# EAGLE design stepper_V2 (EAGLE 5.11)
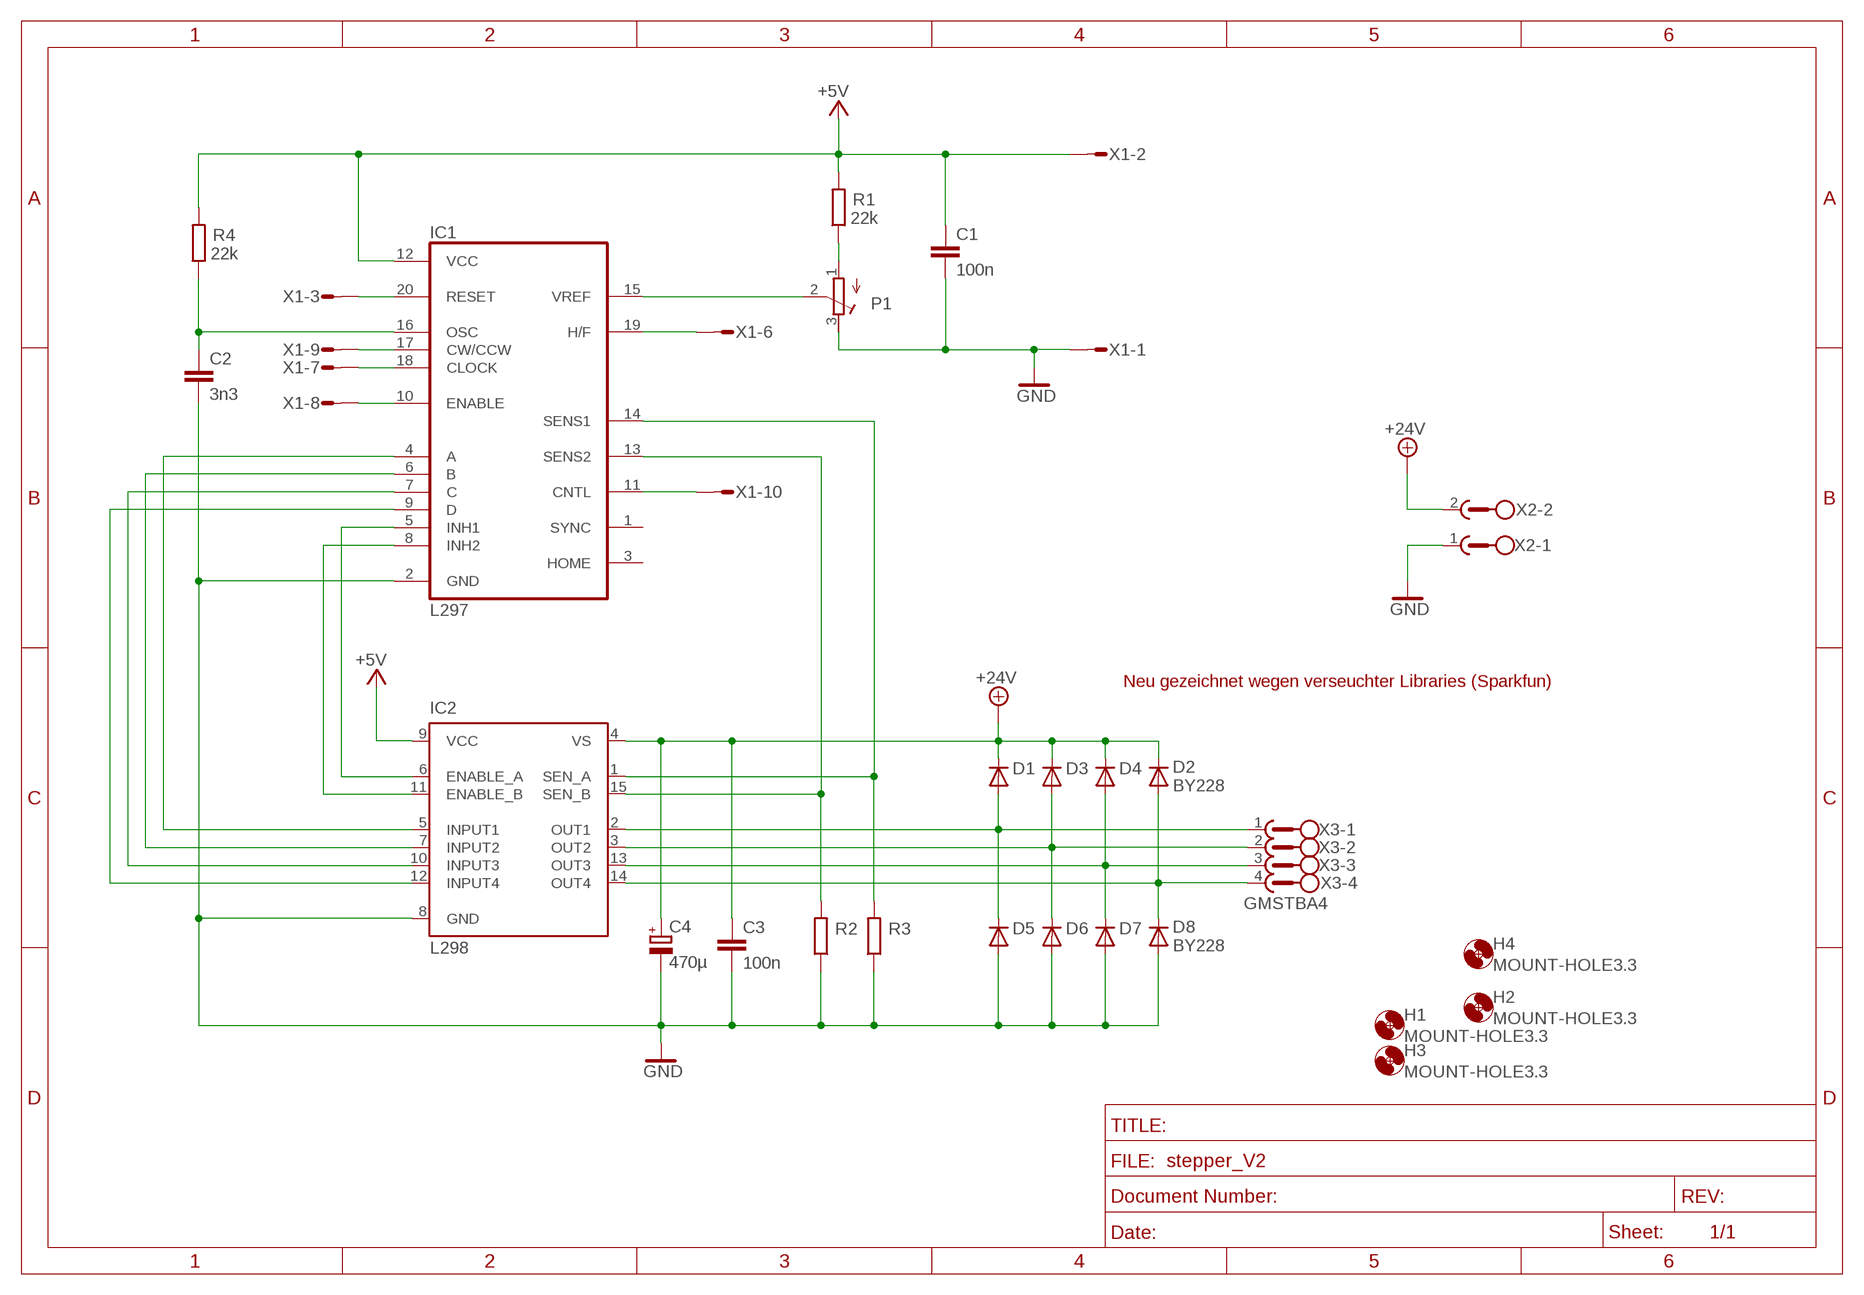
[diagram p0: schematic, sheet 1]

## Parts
C1  100n  C-EU050-024X044  [C050-024X044]
C2  3n3  C-EU050-024X044  [C050-024X044]
C3  100n  C-EU050-024X044  [C050-024X044]
C4  470µ  CPOL-EUE5-10.5  [E5-10,5]
D1  BY228  [SOD64-10]
D2  BY228  [SOD64-10]
D3  BY228  [SOD64-10]
D4  BY228  [SOD64-10]
D5  BY228  [SOD64-10]
D6  BY228  [SOD64-10]
D7  BY228  [SOD64-10]
D8  BY228  [SOD64-10]
H1  MOUNT-HOLE3.3  [3,3]
H2  MOUNT-HOLE3.3  [3,3]
H3  MOUNT-HOLE3.3  [3,3]
H4  MOUNT-HOLE3.3  [3,3]
IC1  L297  [DIL20]
IC2  L298  [MULTIWATT-15]
P1  R-TRIMM64Y  [RTRIM64Y]
R1  22k  R-EU_0207/10  [0207/10]
R2  R-EU_0411/15  [0411/15]
R3  R-EU_0411/15  [0411/15]
R4  22k  R-EU_0207/10  [0207/10]
X1  MICROMATCH-10  [MICROMATCH-10]
X2  GMSTBA2  [GMSTBA2]
X3  GMSTBA4  [GMSTBA4]

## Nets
+5V: C1.1 IC1.12(VCC) IC2.9(VCC) R1.2 R4.2 X1.2
+24V: C3.1 C4.+ D1.C D2.C D3.C D4.C IC2.4(VS) X2.2
GND: C1.2 C2.2 C3.2 C4.- D5.A D6.A D7.A D8.A IC1.2(GND) IC2.8(GND) P1.3(A) R2.1 R3.1 X1.1 X2.1
N$1: IC1.14(SENS1) IC2.1(SEN_A) R3.2
N$2: IC1.13(SENS2) IC2.15(SEN_B) R2.2
N$3: C2.1 IC1.16(OSC) R4.1
N$4: IC1.4(A) IC2.5(INPUT1)
N$5: IC1.6(B) IC2.7(INPUT2)
N$6: IC1.7(C) IC2.10(INPUT3)
N$7: IC1.9(D) IC2.12(INPUT4)
N$8: IC1.5(INH1) IC2.6(ENABLE_A)
N$9: IC1.8(INH2) IC2.11(ENABLE_B)
N$10: IC1.20(RESET) X1.3
N$11: IC1.15(VREF) P1.2(S)
N$12: P1.1(E) R1.1
N$13: IC1.18(CLOCK) X1.7
N$14: D1.A D5.C IC2.2(OUT1) X3.1
N$15: D3.A D6.C IC2.3(OUT2) X3.2
N$16: D4.A D7.C IC2.13(OUT3) X3.3
N$17: D2.A D8.C IC2.14(OUT4) X3.4
N$18: IC1.10(ENABLE) X1.8
N$19: IC1.17(CW/CCW) X1.9
N$20: IC1.11(CNTL) X1.10
N$21: IC1.19(H/F) X1.6
Unconnected: IC1.1(SYNC) IC1.3(HOME) X1.4 X1.5

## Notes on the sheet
- Neu gezeichnet wegen verseuchter Libraries (Sparkfun)

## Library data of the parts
C1-C3 = rcl-JP:C-EU: CAPACITOR, European symbol
C4 = rcl-JP:CPOL-EU: POLARIZED CAPACITOR, European symbol
D1-D8 = diode:BY228: DIODE
H1-H4 = holes:MOUNT-HOLE: MOUNTING HOLE with drill center marker
IC1 = st-microelectronics:L297: STEPPER MOTOR CONTROLLER; MPN: L297/1; OC_FARNELL: 1094209; OC_NEWARK: 56P8258
IC2 = st-microelectronics:L298: DUAL FULL-BRIDGE DRIVER; MPN: L298N; OC_FARNELL: 1589425; OC_NEWARK: 32M1527
P1 = rcl-JP:R-TRIMM: Trimm resistor
R1-R4 = rcl-JP:R-EU_: RESISTOR, European symbol
X1 = con-amp-micromatch:MICROMATCH-10: MicroMaTch 10 8-215464-0 / 1-215464-0 Drawing Number C-215464 DDEController.pdf; MF: FARNELL; MPN: 8-215464-0; OC_FARNELL: 3784654; OC_NEWARK: 19J6430
X2 = con-phoenix-762:GMSTBA2: PHOENIX; MF: FARNELL; MPN: 1757242; OC_FARNELL: 3705171; OC_NEWARK: 71C4161
X3 = con-phoenix-762:GMSTBA4: PHOENIX; MF: FARNELL; MPN: 1757268; OC_FARNELL: 3705195; OC_NEWARK: 71C4163

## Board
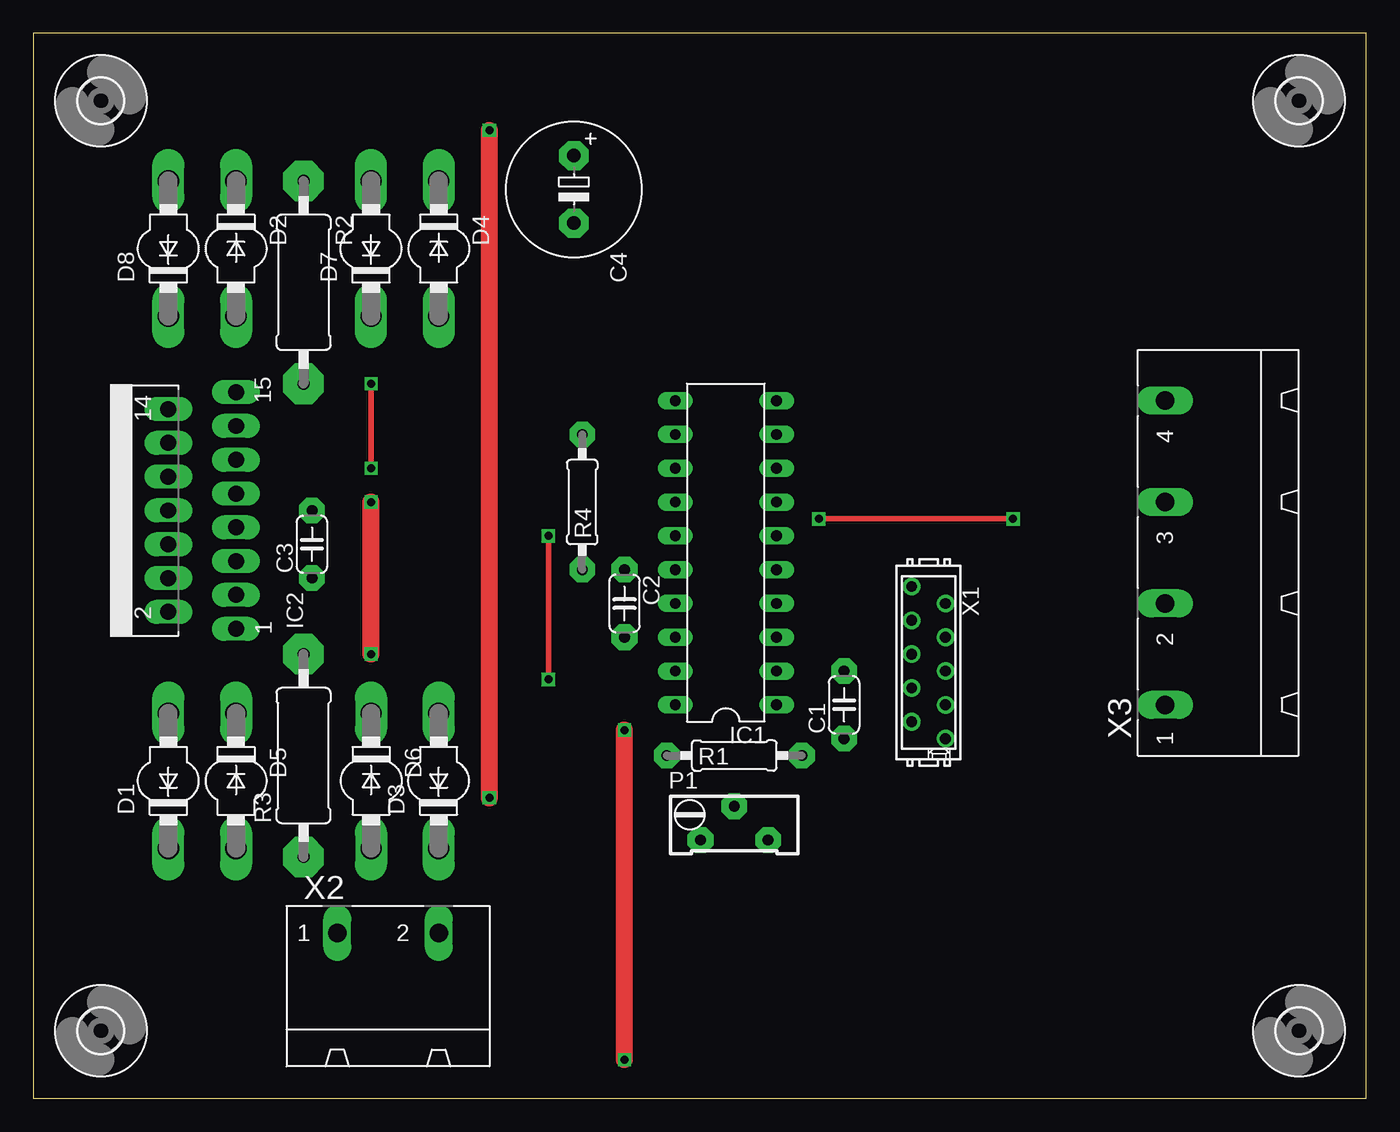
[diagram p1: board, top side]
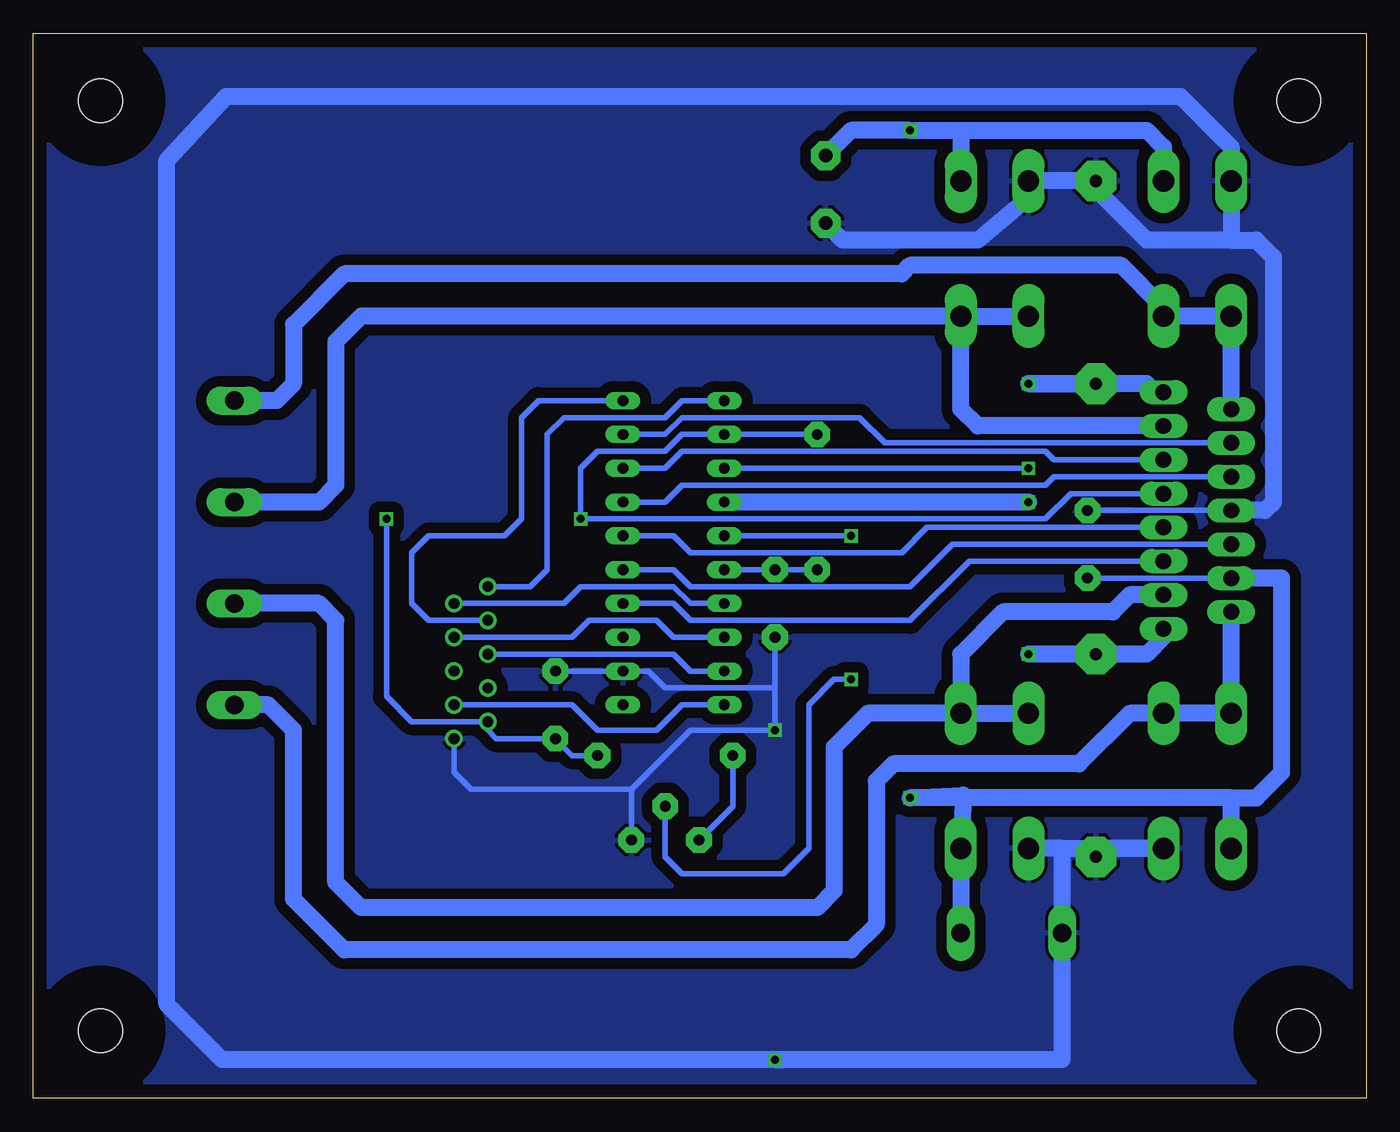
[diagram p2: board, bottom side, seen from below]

Size 100.22 x 80.05 mm. Coordinates in mm from the lower left corner, seen from the top.
Outline: 0,0 100.22,0 100.22,80.04 0,80.04 0,0
Copper layers (1*16): Top 0.035mm / dielectric 1.5mm / Bottom 0.035mm
Design rules "default": minimum track width 10mil, minimum drill 24mil, track to track 8mil, track to pad 8mil, pad to pad 8mil, via to via 8mil, smd to smd 8mil, copper to edge 40mil, drill to drill 8mil, minimum pad ring 10mil, minimum via ring 8mil, stop-mask expansion 4mil, vias tented up to drill 0mil, thermal gap 10mil

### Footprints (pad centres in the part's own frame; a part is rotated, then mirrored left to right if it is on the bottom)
C050-024X044 = drill 0.813 pad 1.93 octagon: 1 -2.54,0; 2 2.54,0
E5-10,5 = drill 1.016 pad 2.184 octagon: + -2.54,0; - 2.54,0
SOD64-10 = drill 1.6 long: A 5.08,0; C -5.08,0
3,3 = hole 3.3: 0,0
DIL20 = drill 0.813 long: 1 -11.43,-3.81; 2 -8.89,-3.81; 3 -6.35,-3.81; 4 -3.81,-3.81; 5 -1.27,-3.81; 6 1.27,-3.81; 7 3.81,-3.81; 8 6.35,-3.81; 9 8.89,-3.81; 10 11.43,-3.81; 11 11.43,3.81; 12 8.89,3.81; 13 6.35,3.81; 14 3.81,3.81; 15 1.27,3.81; 16 -1.27,3.81; 17 -3.81,3.81; 18 -6.35,3.81; 19 -8.89,3.81; 20 -11.43,3.81
MULTIWATT-15 = drill 1.2 long: 1 -8.89,-7.62; 2 -7.62,-2.54; 3 -6.35,-7.62; 4 -5.08,-2.54; 5 -3.81,-7.62; 6 -2.54,-2.54; 7 -1.27,-7.62; 8 0,-2.54; 9 1.27,-7.62; 10 2.54,-2.54; 11 3.81,-7.62; 12 5.08,-2.54; 13 6.35,-7.62; 14 7.62,-2.54; 15 8.89,-7.62
RTRIM64Y = drill 0.813 pad 1.93 octagon: 1 0,-2.54; 2 -2.54,0; 3 0,2.54
0207/10 = drill 0.813 pad 1.93 octagon: 1 -5.08,0; 2 5.08,0
0411/15 = drill 0.914 pad 3.048 octagon: 1 -7.62,0; 2 7.62,0
MICROMATCH-10 = drill 0.813 round: 1 5.715,1.27; 2 4.445,-1.27; 3 3.175,1.27; 4 1.905,-1.27; 5 0.635,1.27; 6 -0.635,-1.27; 7 -1.905,1.27; 8 -3.175,-1.27; 9 -4.445,1.27; 10 -5.715,-1.27
GMSTBA2 = drill 1.397 long: 1 -3.81,5.08; 2 3.81,5.08
GMSTBA4 = drill 1.397 long: 1 -11.43,5.08; 2 -3.81,5.08; 3 3.81,5.08; 4 11.43,5.08

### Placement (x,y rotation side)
C1  60.96,29.57 90 top
C2  44.45,37.2 270 top
C3  20.96,41.64 90 top
C4  40.64,68.31 270 top
D1  10.16,23.86 90 top
D2  15.24,63.87 270 top
D3  30.48,23.86 90 top
D4  30.48,63.87 270 top
D5  15.24,23.86 270 top
D6  25.4,23.86 270 top
D7  25.4,63.87 90 top
D8  10.16,63.87 90 top
H1  5.08,5.08 0 top
H2  5.08,74.98 0 top
H3  95.16,5.08 0 top
H4  95.16,74.98 0 top
IC1  52.07,41 90 top
IC2  7.62,44.18 90 top
P1  52.71,19.41 270 top
R1  52.71,25.76 0 top
R2  20.32,61.32 270 top
R3  20.32,25.76 90 top
R4  41.28,44.81 90 top
X1  67.31,32.75 270 top
X2  26.67,7.35 0 top
X3  90.17,41 90 top

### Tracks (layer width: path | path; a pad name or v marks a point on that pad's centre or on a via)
+5V  (via drill 0.6)
  Top 0.406: v59.06,43.55 v73.66,43.55
  Bottom 0.406: IC2.9 22.22,45.45 24.13,43.55 v59.06,43.55 59.06,47.35 57.78,48.63 52.71,48.63 51.44,49.89 IC1.12 R4.2 | 58.42,25.76 R1.2 59.69,25.76 C1.1 65.41,27.04 66.04,27.67 X1.2 71.75,28.31 73.66,30.21 v73.66,43.55
+24V  (via drill 0.6)
  Top 1.27: v34.29,22.59 v34.29,72.76
  Bottom 0.406: IC2.4 C3.1
  Bottom 1.27: IC2.4 6.35,39.1 6.35,24.49 8.25,22.59 10.16,22.59 | 10.16,21.32 D1.C 10.16,22.59 | 10.16,22.59 v34.29,22.59 30.29,22.78 D3.C X2.2 | 30.48,72.76 16.51,72.76 15.24,71.48 D2.C | 30.48,72.76 D4.C | 30.48,72.76 v34.29,72.76 38.74,72.76 C4.+
GND  (via drill 0.6)
  Top 1.27: v44.45,2.9 v44.45,27.67
  Bottom 0.406: C1.2 IC1.2 53.97,32.11 52.71,30.85 44.45,30.85 | 44.45,30.85 C2.2 | 55.25,23.22 50.8,27.67 v44.45,27.67 44.45,30.85 | X1.1 68.58,24.49 67.31,23.22 55.25,23.22 | 55.25,23.22 P1.3 | IC2.8 C3.2
  Bottom 1.27: IC2.8 7.62,44.18 6.99,44.81 6.99,63.23 8.25,64.5 10.16,64.5 | 10.16,64.5 D8.A 10.16,71.48 13.97,75.29 85.72,75.29 90.17,70.48 90.17,7.08 86,2.9 v44.45,2.9 | C4.- 39.37,64.5 29.21,64.5 25.4,67.68 D7.A R2.1 20.32,68.31 16.51,64.5 10.16,64.5 | 22.86,18.78 D5.A 20.32,18.78 R3.1 | v44.45,2.9 22.86,2.9 X2.1 22.86,18.78 | v44.45,2.9 43.81,2.9 | 22.86,18.78 D6.A
  pour Bottom (isolate 0.813): 0,80.38 100.24,80.38 100.24,0 0,0
N$1  (via drill 0.6)
  Top 1.27: v25.4,33.38 v25.4,44.81
  Bottom 1.27: IC2.1 15.24,34.66 16.51,33.38 R3.2 v25.4,33.38 | v25.4,44.81 IC1.14
N$2  (via drill 0.6)
  Top 0.406: v25.4,53.7 v25.4,47.35
  Bottom 0.406: v25.4,47.35 IC1.13
  Bottom 1.27: IC2.15 15.88,53.07 16.51,53.7 v25.4,53.7 R2.2
N$3
  Bottom 0.406: IC1.16 C2.1 R4.1
N$4
  Bottom 0.406: IC2.5 29.84,40.37 34.29,35.92 50.8,35.92 52.07,37.2 IC1.4
N$5
  Bottom 0.406: IC2.7 33.02,42.91 34.93,41 50.8,41 52.07,42.28 IC1.6
N$6
  Bottom 0.406: IC2.10 23.5,46.72 24.13,46.09 51.44,46.09 52.71,44.81 IC1.7
N$7
  Bottom 0.406: IC2.12 36.19,49.26 38.1,51.17 51.44,51.17 52.71,49.89 IC1.9
N$8
  Bottom 0.406: IC2.6 31.12,41.64 34.29,38.46 50.8,38.46 52.07,39.74 IC1.5
N$9
  Bottom 0.406: IC2.11 23.5,47.99 24.13,48.63 51.44,48.63 52.71,47.35 IC1.8
N$10
  Bottom 0.406: X1.3 59.69,29.58 57.78,27.67 53.34,27.67 51.44,29.58 IC1.20
N$11  (via drill 0.6)
  Top 0.406: v38.74,31.48 v38.74,42.28
  Bottom 0.406: v38.74,31.48 40,31.48 41.91,29.58 41.91,18.78 43.81,16.87 51.44,16.87 52.71,18.15 P1.2 | v38.74,42.28 IC1.15
N$12
  Bottom 0.406: R1.1 47.62,21.95 P1.1
N$13
  Bottom 0.406: X1.7 59.69,34.66 58.42,35.92 53.34,35.92 52.07,34.66 IC1.18
N$14
  Bottom 1.27: IC2.2 D1.A D5.C 17.78,28.94 21.59,25.13 35.56,25.13 36.83,23.86 36.83,13.06 38.74,11.16 76.84,11.16 80.65,14.97 80.65,27.67 82.55,29.58 X3.1
N$15
  Bottom 1.27: IC2.3 17.78,37.83 19.05,36.56 27.31,36.56 30.48,33.38 D3.A | D3.A D6.C | D3.A 37.47,28.94 40,26.4 40,15.61 41.28,14.34 75.56,14.34 77.47,16.24 77.47,35.92 78.74,37.2 X3.2
N$16
  Bottom 1.27: IC2.13 29.21,50.53 30.48,51.8 D4.A | D4.A D7.C | D4.A 75.56,58.78 77.47,56.88 77.47,46.09 78.74,44.81 X3.3
N$17
  Bottom 1.27: IC2.14 D8.C D2.A 15.24,59.42 18.41,62.6 34.29,62.6 34.93,61.96 76.84,61.96 80.65,58.15 80.65,53.7 81.91,52.43 X3.4
N$18
  Bottom 0.406: IC1.10 62.23,52.43 63.5,51.17 63.5,43.55 64.77,42.28 70.49,42.28 71.75,41 71.75,37.2 70.49,35.92 X1.8
N$19
  Bottom 0.406: X1.9 60.33,37.2 59.06,38.46 52.07,38.46 50.8,37.2 IC1.17
N$20
  Bottom 0.406: IC1.11 51.44,52.43 52.71,51.17 60.33,51.17 61.59,49.89 61.59,39.74 62.87,38.46 X1.10
N$21
  Bottom 0.406: IC1.19 50.8,32.11 52.07,33.38 X1.6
